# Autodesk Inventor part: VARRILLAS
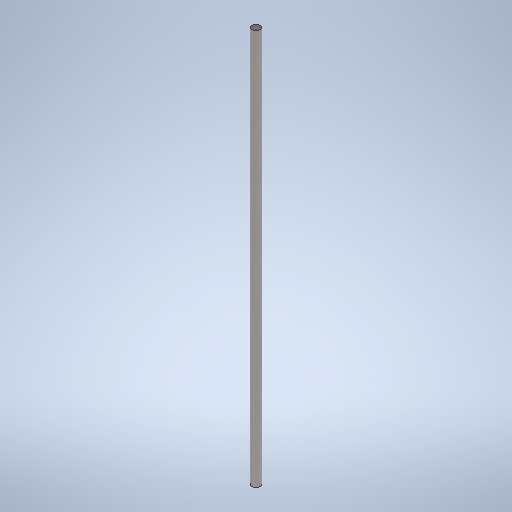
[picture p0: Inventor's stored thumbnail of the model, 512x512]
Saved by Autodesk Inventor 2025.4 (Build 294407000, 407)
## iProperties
Created: 2026-04
Part Number: VARRILLAS
Material: Stainless Steel
Document SubType Name: Modeling
Designer: PC
Density: 8 g/cm^3
Appearance: Semi-Polished
Author: PC
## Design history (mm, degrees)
sketch "Sketch1"
  geometry: C1 r 4 at (0, 0); 1 further point
  constraints: 1 centre point, 1 coincident
  dimensions: "d0" = 8 diameter of C1
extrude "Extrusion1" new body sketch "Sketch1" distance "d1" = 400; taper "d2" = 0 deg
body "Solid1"
